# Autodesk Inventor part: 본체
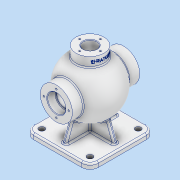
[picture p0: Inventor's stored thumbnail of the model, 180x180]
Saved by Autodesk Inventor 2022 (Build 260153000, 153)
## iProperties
Created: 2024-04
Part Number: 본체
Material: 알루미늄 6061
Document SubType Name: Modeling
Designer: Admin
Mass: 1526.9 g
Surface Area: 1171.86 cm^2
Volume: 565.52 cm^3
Density: 2.7 g/cm^3
Appearance: 알루미늄 - 평지
Author: Admin
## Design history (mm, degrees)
sketch "스케치1"
  geometry: C1 r 54 at (0, 0); 1 further point
  constraints: 1 centre point, 1 coincident
  dimensions: "d0" = 108 diameter of C1
extrude "돌출1" new body sketch "스케치1" stored distance "d1" = 108; taper "d2" = 0 deg
fillet "모깎기1" dims "d3" = 54
node "작업 평면2"
sketch "스케치2"
  geometry: L1 (-46.5, -62.5)-(46.5, -62.5); L2 (62.5, -46.5)-(62.5, 46.5); L3 (46.5, 62.5)-(-46.5, 62.5); L4 (-62.5, 46.5)-(-62.5, -46.5); L5 (-62.5, -62.5)-(62.5, 62.5); L6 (62.5, -62.5)-(-62.5, 62.5); A1 r 16 centre (46.5, 46.5) between (62.5, 46.5) and (46.5, 62.5); A2 r 16 centre (46.5, -46.5) between (46.5, -62.5) and (62.5, -46.5); A3 r 16 centre (-46.5, -46.5) between (-62.5, -46.5) and (-46.5, -62.5); A4 r 16 centre (-46.5, 46.5) between (-46.5, 62.5) and (-62.5, 46.5); 1 further point
  constraints: 12 end point, 8 point on circle, 8 point on line, 8 tangent, 4 centre point, 3 equal radius, 2 midpoint, 2 parallel, 1 horizontal, 1 perpendicular
  dimensions: "d6" = 125 distance of L6.start L5.end; "d7" = 125 distance of L5.start L6.start (= d6); "d8" = 16 radius of A1
extrude "돌출2" join sketch "스케치2" distance "d9" = 10; taper "d10" = 0 deg
sketch "스케치3"
  geometry: L1 (-112.8, 0)-(81.8, 0) reference; L2 (0, -87.5)-(0, 87.5) reference; L3 (-85, 87.5)-(-85, -87.5) reference; L4 (-85, 46.5)-(-85, 62.5) reference; L5 (0, 23.202)-(0, -23.202); L6 (-85, -62.5)-(-85, -46.5) reference; L7 (-85, 62.5)-(-75, 62.5) reference; L8 (-75, 46.5)-(-75, 62.5) reference; L9 (-75, -62.5)-(-75, -46.5) reference; L10 (-85, -46.5)-(-85, 46.5) reference; L11 (0, 23.202)-(-75, 50.5); L12 (-75, 50.5)-(-75, -50.5); L13 (-75, -50.5)-(0, -23.202); L14 (-75, -46.5)-(-75, 46.5) reference; 5 further points
  constraints: 8 end point, 3 midpoint, 2 symmetric about line, 1 parallel, 1 point on line, 1 vertical
  dimensions: "d13" = 20 deg angle of L7 L11; "d14" = 12 distance from line of L7 L11.end
extrude "돌출3" join sketch "스케치3" stored distance "d15" = 8; taper "d16" = 0 deg
sketch "스케치4"
  geometry: L1 (46.5, -75)-(-46.5, -75) reference; L2 (0, -112.8)-(0, 81.8) reference; L3 (-87.5, 0)-(87.5, 0) reference; L4 (-23.202, 0)-(23.202, 0); L5 (23.202, 0)-(50.5, -75); L6 (50.5, -75)-(-50.5, -75); L7 (-50.5, -75)-(-23.202, 0); L8 (-62.5, -85)-(-62.5, -75) reference; 3 further points
  constraints: 8 end point, 4 midpoint, 2 symmetric about line, 1 horizontal
  dimensions: "d17" = 20 deg angle of L8 L7; "d18" = 12 distance from line of L8 L6.end
extrude "돌출4" join sketch "스케치4" stored distance "d19" = 8; taper "d20" = 0 deg
node "작업 평면3"
sketch "스케치5"
  geometry: C1 r 31 at (0, 0); 1 further point
  constraints: 1 centre point, 1 coincident
  dimensions: "d22" = 62 diameter of C1
extrude "돌출5" join sketch "스케치5" distance "d23" = 130; taper "d24" = 0 deg
node "작업 평면4"
sketch "스케치6"
  geometry: C1 r 27 at (0, 0); 1 further point
  constraints: 1 centre point, 1 coincident
  dimensions: "d26" = 54 diameter of C1
extrude "돌출6" join sketch "스케치6" stored distance "d27" = 130; taper "d28" = 0 deg
sketch "스케치9"
  geometry: C1 r 15 at (0, 0); 1 further point
  constraints: 1 centre point, 1 coincident
  dimensions: "d29" = 30 diameter of C1
extrude "돌출7" cut sketch "스케치9" stored distance "d31" = 10; taper "d32" = 0 deg
sketch "스케치11"
  geometry: C1 r 13 at (0, 0); 1 further point
  constraints: 1 centre point, 1 coincident
  dimensions: "d33" = 26 diameter of C1
extrude "돌출8" cut sketch "스케치11" stored distance "d34" = 10; taper "d35" = 0 deg; dims "d6" = 125, "d7" = 125 (= d6), "d8" = 16
sketch "스케치12"
  geometry: L1 (0, -91)-(0, 91) reference; L2 (0, -128.405)-(0, 139.748); A1 r 44 centre (0, 0) between (0, -44) and (0, 44); 3 further points
  constraints: 5 point on line, 2 end point, 2 point on circle, 1 centre point, 1 coincident
  dimensions: "d36" = 44 radius of A1
revolve "회전1" sketch "스케치12" stored, may be unused: angle "d37" = 90 deg
sketch "스케치13"
  geometry: C1 r 17.5 at (0, 0); 1 further point
  constraints: 1 centre point, 1 coincident
  dimensions: "d38" = 35 diameter of C1
extrude "돌출9" cut sketch "스케치13" distance "d39" = 16; taper "d40" = 0 deg
sketch "스케치14"
  geometry: L1 (87.5, 0)-(-87.5, 0) reference; L2 (0, -115)-(0, 95) reference; 2 further points
  constraints: 1 point on line
  dimensions: "d41" = 24 distance from line of L1 point (0, 24)
hole "구멍1" sketch "스케치14" at (0, 24) diameter "d42" = 3.242; stored, may be unused: countersink angle "d46" = 90 deg, drill point angle "d48" = 118 deg; dims "d43" = 12, "d44" = 4, "d45" = 2, "d47" = 15
sketch "스케치15"
  geometry: L1 (0, 91)-(0, -91) reference; 2 further points
  constraints: 1 point on line
  dimensions: "d52" = 20 distance of point (0, 0) point (0, -20)
hole "구멍2" sketch "스케치15" at (0, -20) diameter "d53" = 3.242; stored, may be unused: countersink angle "d57" = 90 deg, drill point angle "d59" = 118 deg; dims "d54" = 9, "d55" = 4, "d56" = 2, "d58" = 11
fillet "모깎기2" dims "d63" = 3
fillet "모깎기3" dims "d64" = 3
chamfer "모따기1" distance "d65" = 1; stored, may be unused: second distance "d66" = 2, angle "d67" = 45 deg
sketch "스케치16"
  geometry: A1 r 16 centre (-46.5, -46.5) between (-62.5, -46.5) and (-46.5, -62.5) reference; A2 r 16 centre (-46.5, 46.5) between (-46.5, 62.5) and (-62.5, 46.5) reference; A3 r 16 centre (46.5, 46.5) between (62.5, 46.5) and (46.5, 62.5) reference; A4 r 16 centre (46.5, -46.5) between (46.5, -62.5) and (62.5, -46.5) reference; 5 further points
  constraints: 4 coincident
hole "구멍3" sketch "스케치16" at (-46.5, -46.5), (-46.5, 46.5), (46.5, 46.5), (46.5, -46.5) diameter "d68" = 11; stored, may be unused: countersink angle "d72" = 90 deg, drill point angle "d74" = 118 deg; dims "d69" = 9, "d70" = 4, "d71" = 2, "d73" = 11
fillet "모깎기4" dims "d75" = 3
node "작업 평면5"
sketch "스케치17"
  geometry: L1 (-115, 0)-(95, 0) reference; L2 (65, -27)-(65, 27) reference; 2 further points
  constraints: 1 point on line, 1 other
  dimensions: "d77" = 9 distance from line of L2 point (56, 0)
feature "엠보싱1" sketch "스케치17" dims "d6" = 125, "d7" = 125 (= d6), "d8" = 16, "d78" = 0.5, "d79" = 0
node "솔리드1"
mirror "미러1"
pattern_circular "원형 패턴1" dims angle "d50" = 360 deg
mirror "미러2"
pattern_circular "원형 패턴2" dims angle "d61" = 360 deg
feature "A9D066F2-1C7D-4E18-AEED-F7BC21143FA4" dims "d68" = 11, "d69" = 9, "d70" = 4, "d71" = 2, "d72" = 90 deg, "d73" = 11, "d74" = 118 deg
other parameters: "d5" = -85, "d21" = 65, "d25" = 65, "d76" = 182.5
